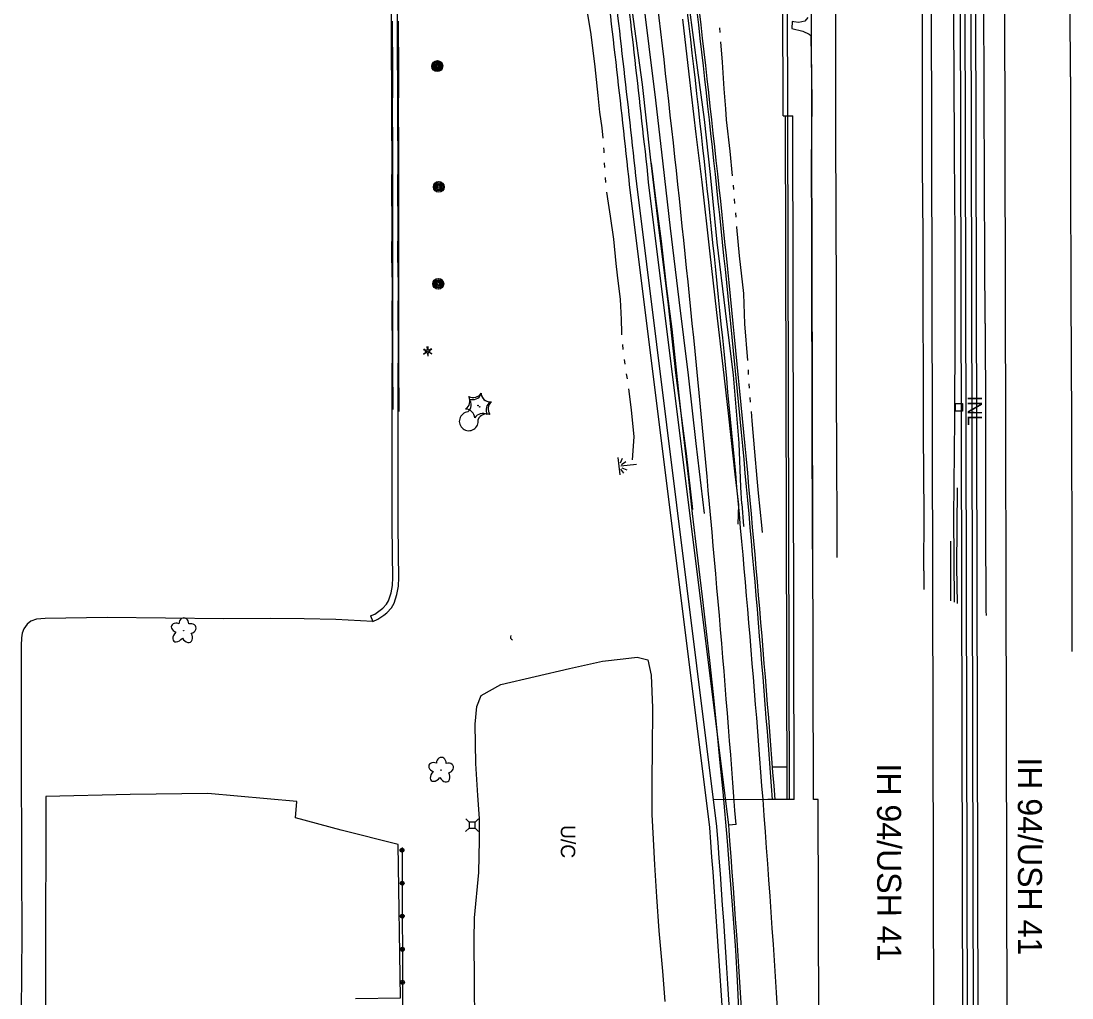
# Model space of a CAD drawing. Extents: x 588843 to 2552415, y 180129 to 269402.
# Drawn here: x 593621.5 to 594059.5, y 184401.2 to 184808.3 of the extents above; entities that cross this region are included whole.
import ezdxf

# ---------------------------------------------------------------- set-up
doc = ezdxf.new("R2010")
doc.units = 0
for name, color, linetype in [('Default', 7, 'Continuous'), ('E_AREA', 7, 'Continuous'), ('E_AREA_Text', 7, 'Continuous'), ('E_BMGRD_P', 7, 'Continuous'), ('E_DRN', 7, 'Continuous'), ('E_DRN_Text', 7, 'Continuous'), ('E_DWY', 7, 'Continuous'), ('E_LAND_Vegetation', 7, 'Continuous'), ('E_LTG', 7, 'Continuous'), ('E_MISCPROP', 7, 'Continuous'), ('E_RDWY', 7, 'Continuous'), ('E_RDWY_C_and_G', 7, 'Continuous'), ('E_RDWY_Gravel', 7, 'Continuous'), ('E_RDWY_Text', 7, 'Continuous'), ('E_STRUCT', 7, 'Continuous'), ('E_UTL_AG_Bold', 7, 'Continuous'), ('E_WTR_P', 7, 'Continuous'), ('E_WTR_Wetland', 7, 'Continuous'), ('P_RDWY_BarrierConc', 7, 'Continuous'), ('P_RDWY_C_and_G', 7, 'Continuous'), ('P_RDWY_C_and_GBack', 7, 'Continuous'), ('P_RDWY_C_and_GFace', 7, 'Continuous'), ('P_RDWY_LaneEdge', 7, 'Continuous'), ('P_RDWY_PavtEdge', 7, 'Continuous'), ('P_RDWY_ShldAgg', 7, 'Continuous'), ('P_RDWY_ShldPaved', 7, 'Continuous')]:
    doc.layers.add(name, color=color, linetype=linetype)

# ---------------------------------------------------------------- blocks, each defined once
blk = doc.blocks.new('DTRE')
at = {"layer": 'Default'}
blk.add_circle((-0.18, 0), 0.183, dxfattribs=at)
for centre, major_axis, ratio in [((-1.87, 5.32), (1.36, -4.98), 0.782863), ((-5.87, 0.15), (4.93, -0.12), 0.832022), ((4.06, 2.74), (-5.27, -2.93), 0.691916), ((-2.49, -5.24), (1.8, 4.86), 0.716896), ((3.54, -3.71), (-5.01, 4.58), 0.560249)]:
    blk.add_ellipse(centre, major_axis=major_axis, ratio=ratio, start_param=1.570796, end_param=4.712389, dxfattribs=at)
blk = doc.blocks.new('LPOL')
at = {"layer": 'Default'}
for p, q in [((-4, 0), (-1.5, 0)), ((-0.75, 1.3), (-2, 3.46)), ((0.75, 1.3), (2, 3.46)), ((1.5, 0), (4, 0)), ((-2, -3.46), (-0.75, -1.3)), ((2, -3.46), (0.75, -1.3))]:
    blk.add_line(p, q, dxfattribs=at)
for radius in [1.5, 1.5, 1.5, 0.125]:
    blk.add_circle((0, 0), radius, dxfattribs=at)
blk = doc.blocks.new('POLE')
at = {"layer": 'Default'}
for radius in [4.46, 3.35, 2.23, 1.12]:
    blk.add_circle((0, 0), radius, dxfattribs=at)
blk = doc.blocks.new('CTRE')
at = {"layer": 'Default'}
blk.add_circle((0, 0), 0.223, dxfattribs=at)
for centre, start, end in [((-11.97, 8.96), 280.2067, 5.97162), ((1.81, 14.92), 220.21132, 305.97623), ((-13.83, -5.9), 340.21132, 65.97623), ((13.83, 5.89), 160.21133, 245.97624), ((-1.81, -14.93), 40.21133, 125.97624), ((12.03, -9.04), 185.92721, 100.25111)]:
    blk.add_arc(centre, 7.87, start, end, dxfattribs=at)
blk = doc.blocks.new('PED')
at = {"layer": 'Default'}
for p, q in [((-2.5, 2.5), (-5.33, 5.33)), ((2.5, 2.5), (5.33, 5.33)), ((-2.5, -2.5), (-5.33, -5.33)), ((2.5, -2.5), (5.33, -5.33))]:
    blk.add_line(p, q, dxfattribs=at)
blk.add_lwpolyline([(-2.5, -2.5), (2.5, -2.5), (2.5, 2.5), (-2.5, 2.5)], close=True, dxfattribs=at)
blk = doc.blocks.new('CULV2')
at = {"layer": 'E_DRN'}
blk.add_arc((19.7, 14.8), 24.6, 216.8699, 323.1301, dxfattribs=at)
blk = doc.blocks.new('UCA_1')
at = {"layer": 'E_AREA_Text'}
blk.add_text('U/C', height=12, dxfattribs=at).set_placement((-15.33, -6))
blk = doc.blocks.new('INLT_47_1')
at = {"layer": 'E_DRN_Text'}
blk.add_text('INL', height=39.37, dxfattribs=at).set_placement((-36.2, -19.7))
blk = doc.blocks.new('MAR_3')
at = {"layer": 'E_WTR_Wetland'}
for p, q in [((-0.1, 48.7), (-0.1, 5.3)), ((-24, 0), (23.7, 0)), ((-20, 11.5), (-8.1, 4.8)), ((-4.5, 7.8), (-11.6, 20.2)), ((4.6, 7.8), (11.7, 20.2)), ((20, 11.5), (8.1, 4.8))]:
    blk.add_line(p, q, dxfattribs=at)
blk = doc.blocks.new('LPOL_4')
at = {"layer": 'E_LTG'}
for p, q in [((-13.1, 0), (-4.9, 0)), ((-2.5, 4.3), (-6.6, 11.4)), ((2.5, 4.3), (6.6, 11.4)), ((4.9, 0), (13.1, 0)), ((-6.6, -11.4), (-2.5, -4.3)), ((6.6, -11.4), (2.5, -4.3))]:
    blk.add_line(p, q, dxfattribs=at)
for radius in [4.92, 4.92, 4.92, 0.41]:
    blk.add_circle((0, 0), radius, dxfattribs=at)
blk = doc.blocks.new('POLE_3')
at = {"layer": 'E_MISCPROP'}
for radius in [14.6, 11, 7.32, 3.66]:
    blk.add_circle((0, 0), radius, dxfattribs=at)
blk = doc.blocks.new('CTRE_4')
at = {"layer": 'E_LAND_Vegetation'}
blk.add_circle((0, 0), 0.733, dxfattribs=at)
for centre, start, end in [((-39.3, 29.4), 280.2067, 5.9716), ((5.9, 49), 220.2113, 305.9762), ((-45.4, -19.3), 340.2113, 65.9762), ((45.4, 19.3), 160.2113, 245.9762), ((-5.9, -49), 40.2113, 125.9762), ((39.5, -29.6), 100.2511, 185.9272)]:
    blk.add_arc(centre, 25.8, start, end, dxfattribs=at)

msp = doc.modelspace()

# ---------------------------------------------------------------- linework, layer by layer
at = {"layer": 'E_AREA'}
msp.add_lwpolyline([(593810.77, 184373.26), (593810.42, 184425.33), (593810.56, 184434.56), (593812.35, 184453.43), (593812.6, 184466.99), (593812.54, 184475.91), (593811.88, 184485.55), (593811.1, 184498.88), (593810.79, 184515.27), (593811.49, 184522.6), (593813.24, 184527.19), (593821.47, 184531.84), (593850.1, 184538.48), (593863.86, 184541.49), (593872.45, 184542.57), (593878.31, 184543.15), (593882.76, 184542.11), (593884.2, 184535.68), (593884.7, 184522.05), (593884.5, 184504.28), (593884.37, 184492.57), (593884.45, 184477.64), (593884.95, 184467.29), (593885.57, 184456.69), (593886.35, 184443.37), (593887.4, 184429.14), (593888.88, 184412.4), (593889.82, 184399.75)], dxfattribs=at)
at = {"layer": 'E_BMGRD_P'}
msp.add_lwpolyline([(593780.31, 184463.92), (593780.54, 184391.32), (593780.57, 184330.59), (593780.68, 184274.1), (593780.2, 184209.84), (593780.05, 184155.08), (593779.93, 184133.47)], dxfattribs=at)
for centre, major_axis in [((593780.31, 184462.77), (0.015, 0.802)), ((593780.31, 184462.77), (0.007, 0.404)), ((593780.36, 184449), (0.015, 0.802)), ((593780.36, 184449), (0.007, 0.404)), ((593780.4, 184435.24), (0.015, 0.802)), ((593780.4, 184435.24), (0.007, 0.404)), ((593780.45, 184421.47), (0.015, 0.802)), ((593780.45, 184421.47), (0.007, 0.404)), ((593780.49, 184407.7), (0.015, 0.802)), ((593780.49, 184407.7), (0.007, 0.404))]:
    msp.add_ellipse(centre, major_axis=major_axis, ratio=0.996114, dxfattribs=at)
at = {"layer": 'E_DRN'}
msp.add_lwpolyline([(594013.86, 184648.93), (594013.94, 184645.78), (594011.04, 184645.71), (594010.96, 184648.86)], close=True, dxfattribs=at)
at = {"layer": 'E_DWY'}
for points in [[(593776.15, 184749.37), (593776.03, 184767.18), (593776.04, 184780.71), (593775.97, 184794.73), (593775.97, 184811.77)], [(593778.65, 184749.39), (593778.53, 184767.19), (593778.54, 184780.71), (593778.47, 184794.73), (593778.47, 184811.77)], [(593776.19, 184808.3), (593776.28, 184786.65), (593776.22, 184765.56), (593776.28, 184762.73), (593776.35, 184744.69), (593776.37, 184730.05), (593776.29, 184709.98), (593776.31, 184688.06), (593776.35, 184665.26), (593776.43, 184646.46)], [(593778.69, 184808.31), (593778.78, 184786.65), (593778.72, 184765.59), (593778.78, 184762.76), (593778.85, 184744.69), (593778.87, 184730.05), (593778.79, 184709.98), (593778.81, 184688.06), (593778.85, 184665.27), (593778.94, 184645.66), (593778.94, 184645.61)], [(593767.19, 184560.4), (593768.98, 184561.17), (593771.24, 184562.73), (593772.3, 184563.56), (593773.86, 184565.27), (593774.71, 184566.73), (593775.76, 184569.96), (593776.29, 184573.05), (593776.45, 184576.4), (593776.4, 184585.97), (593776.21, 184598.89), (593776.23, 184612.99), (593776.2, 184630.31), (593776.27, 184643.59), (593776.22, 184658.3), (593776.29, 184673.42), (593776.21, 184685.03), (593776.36, 184698.52), (593776.13, 184710.52), (593776.19, 184722.71), (593776.12, 184739.48), (593776.15, 184749.37)], [(593768.18, 184558.11), (593770.2, 184558.97), (593772.72, 184560.71), (593774.01, 184561.72), (593775.88, 184563.78), (593777, 184565.7), (593778.19, 184569.36), (593778.78, 184572.77), (593778.95, 184576.35), (593778.9, 184586), (593778.71, 184598.91), (593778.73, 184612.99), (593778.7, 184630.31), (593778.77, 184643.58), (593778.72, 184658.29), (593778.79, 184673.42), (593778.71, 184685.03), (593778.86, 184698.53), (593778.63, 184710.53), (593778.69, 184722.71), (593778.62, 184739.48), (593778.65, 184749.39)], [(593767.19, 184560.4), (593768.18, 184558.11), (593752.76, 184558.88), (593739.58, 184559.14), (593725.35, 184559.27), (593705.98, 184559.23), (593657.46, 184559.7), (593631.52, 184559.25), (593627.9, 184559), (593625.55, 184558.15), (593624.05, 184556.99), (593622.66, 184555.07), (593621.99, 184553.25), (593621.65, 184551.31), (593621.53, 184548.04), (593621.56, 184505.7), (593621.71, 184455.38), (593621.85, 184427.62), (593621.52, 184395.34)], [(593760.97, 184400.9), (593779.66, 184401.18), (593778.67, 184465.17), (593755, 184471.17), (593735.86, 184476.24), (593736.4, 184483.08), (593699.43, 184486.32), (593666.97, 184486.03), (593631.87, 184485.11), (593631.69, 184413.71), (593631.67, 184373.35)]]:
    msp.add_lwpolyline(points, dxfattribs=at)
at = {"layer": 'E_RDWY'}
for points in [[(594023.34, 184682.26), (594023.25, 184709.56), (594023.04, 184739.91), (594023, 184778.2), (594022.82, 184818.16), (594022.67, 184861.06), (594022.65, 184896.86), (594022.58, 184934.07), (594022.62, 184972.8), (594022.48, 185013.2), (594022.39, 185057.62), (594022.2, 185103.22), (594022.12, 185147.96), (594021.99, 185189.79), (594021.86, 185234.19), (594021.61, 185282.87), (594021.71, 185325.21), (594022.01, 185370.2), (594022.14, 185393.45)], [(594058.92, 184785.01), (594058.82, 184814.32), (594058.74, 184856.48), (594058.72, 184888.42), (594058.64, 184920.39), (594058.61, 184955.57), (594058.47, 184990.54), (594058.38, 185026.41), (594058.18, 185063.12), (594058.32, 185096.32), (594058.13, 185129.63), (594058.04, 185158.77), (594058.03, 185187.99), (594057.99, 185226.54), (594057.97, 185253.66), (594057.64, 185280.67), (594057.82, 185338.96), (594057.67, 185356.32), (594057.68, 185378.51)], [(593906.33, 184603.12), (593902.92, 184632.27), (593899.65, 184660.76), (593895.88, 184692.09), (593892.24, 184722.03), (593889.11, 184748.84), (593886.03, 184775.27), (593883.34, 184797.63), (593880.29, 184822.58), (593876.81, 184852.9), (593873.76, 184879.56), (593870.15, 184910.6), (593867.01, 184938.51), (593863.39, 184971.22), (593860.52, 184996.66), (593857.95, 185023.1), (593855.61, 185048.62), (593852.95, 185083.15), (593851.06, 185119.17), (593850.2, 185152.54), (593849.72, 185184.93), (593849.66, 185210.92)], [(593961.66, 184584.71), (593961.61, 184597.79), (593961.51, 184627.2), (593961.41, 184654.59), (593961.38, 184693.93), (593961.28, 184727.64), (593961.06, 184762.04), (593961.05, 184801.45), (593960.9, 184844.07), (593960.93, 184878.06), (593960.81, 184909.45), (593960.59, 184947.71), (593960.4, 184982.2), (593960.44, 185016.64), (593960.35, 185048.64), (593960.38, 185082.04), (593960.11, 185118.13), (593960.11, 185156.58), (593960.05, 185202.8)], [(593997.74, 184579.23), (593997.88, 184602.77), (593997.66, 184636.35), (593997.62, 184658.68), (593997.56, 184689.47), (593997.45, 184718.98), (593997.28, 184748.08), (593997.28, 184776.99), (593997.26, 184803.01), (593997.03, 184828.04), (593997.04, 184853.56), (593997.01, 184872.9), (593996.93, 184898.91), (593996.95, 184927.32), (593996.91, 184954.55), (593996.75, 184983.68), (593996.74, 185009.24), (593996.75, 185039.17), (593996.69, 185065.27), (593996.43, 185092.39), (593996.46, 185124.29), (593996.36, 185155.17), (593996.3, 185186.28)], [(593897.19, 184809.08), (593899.84, 184786.18), (593902.76, 184761.17), (593905.25, 184741.14), (593908.51, 184712.48), (593911.44, 184686.85), (593913.95, 184664.33), (593916.36, 184643.6), (593919.08, 184619.5), (593920.48, 184606.75)], [(594058.92, 184785.01), (594058.88, 184744.07), (594059.07, 184694.66), (594059.28, 184640.64), (594059.48, 184584.47), (594059.53, 184545.63)], [(594023.34, 184682.26), (594023.42, 184643.54), (594023.53, 184599.58), (594023.69, 184562.57), (594023.7, 184560.56)], [(593997.74, 184579.23), (593997.77, 184571.36)]]:
    msp.add_lwpolyline(points, dxfattribs=at)
at = {"layer": 'E_RDWY_C_and_G'}
for points in [[(593920.48, 184606.75), (593920.23, 184598.56)], [(593922, 184607.06), (593922.69, 184597.87), (593922.71, 184597.72)]]:
    msp.add_lwpolyline(points, dxfattribs=at)
at = {"layer": 'E_RDWY_Gravel'}
for points in [[(593901.51, 184604.7), (593898.89, 184628.12), (593894.48, 184661.7), (593891.4, 184689.97), (593887.19, 184723.53), (593883.88, 184751.61), (593880.49, 184781.82), (593876.8, 184809.14), (593872.09, 184846.12), (593868.13, 184880.53), (593863.95, 184918.6), (593860.69, 184948.98), (593857.26, 184982.17), (593854.92, 185005.52), (593852.06, 185032.14), (593849.54, 185060.16), (593847.3, 185092.17), (593846.04, 185116.76), (593845.29, 185144.85), (593844.4, 185173.99), (593844.28, 185200.35)], [(593921.9, 184607.05), (593921.46, 184614), (593920.76, 184632.41), (593918.41, 184660.66), (593915.16, 184687.58), (593911.66, 184716.17), (593908.93, 184744.38), (593906.44, 184767.23), (593903.57, 184787.84), (593900.04, 184815.06)], [(593949.5, 184809.8), (593948.2, 184808.25), (593945.74, 184807.72), (593943.63, 184807.97), (593942.94, 184808.04), (593942.74, 184805.25), (593947.41, 184804.12), (593950.05, 184802.84), (593950.73, 184802.31), (593951.07, 184775.26), (593950.85, 184747.91), (593950.97, 184721.39), (593951.02, 184689.79), (593951.09, 184659.68), (593951.11, 184632.56), (593951.21, 184602.44), (593951.27, 184588.18)], [(593884.18, 184749.05), (593885.95, 184734.32), (593888.25, 184716.51), (593890.39, 184697.91), (593892.71, 184679.87), (593894.39, 184664.15), (593895.66, 184652.37), (593897.4, 184637.41), (593899.65, 184617.33), (593901.24, 184603.07), (593902.64, 184591.34), (593905.43, 184568.31), (593906.88, 184555.12), (593908.47, 184541.75), (593909.96, 184527.7), (593911.46, 184512.53), (593912.57, 184500.57), (593914.01, 184487.1), (593915.76, 184466.58), (593916.76, 184453.61), (593917.86, 184439.82), (593919.24, 184421.13), (593919.93, 184408.32), (593920.5, 184396.58)], [(594011.74, 184613.72), (594011.45, 184580.83), (594011.72, 184565.55)], [(594008.93, 184591.49), (594008.96, 184566.69)]]:
    msp.add_lwpolyline(points, dxfattribs=at)
at = {"layer": 'E_STRUCT'}
for points in [[(594007.57, 185399.67), (594008.45, 185379.96), (594008.58, 185346.39), (594008.62, 185302.69), (594008.59, 185270.63), (594008.85, 185235.62), (594008.95, 185198.53), (594009.16, 185161.43), (594009.23, 185125.36), (594009.42, 185092.69), (594009.24, 185064.46), (594009.4, 185031), (594009.61, 184996.11), (594009.68, 184962.18), (594009.8, 184932.13), (594009.91, 184898.48), (594010.17, 184858.49), (594010.07, 184823.02), (594010.32, 184787.4), (594010.45, 184753.11), (594010.69, 184718.6), (594010.65, 184679.45), (594010.55, 184642.38), (594010.12, 184601.49)], [(594010.12, 184601.49), (594010.41, 184566.09)]]:
    msp.add_lwpolyline(points, dxfattribs=at)
at = {"layer": 'E_WTR_P'}
for points in [[(593856.64, 184818.82), (593857.32, 184812.83), (593859.06, 184802.75), (593860.6, 184789.22)], [(593912.65, 184805.42), (593912.75, 184803.49)], [(593913.05, 184799.64), (593913.75, 184791.12), (593914.44, 184780.11), (593915.07, 184771.69)], [(593860.6, 184789.22), (593860.9, 184786.6), (593861.94, 184777.29), (593862.64, 184770.28), (593863.53, 184763.77), (593863.94, 184759.53)], [(593915.07, 184771.69), (593915.41, 184767.09), (593916.91, 184754.06), (593917.89, 184743.82)], [(593864.33, 184755.43), (593864.44, 184754.34), (593864.47, 184753.38)], [(593864.61, 184749.26), (593864.68, 184747.2)], [(593864.96, 184743.09), (593865.16, 184741.04)], [(593865.59, 184736.94), (593866.2, 184732.38), (593867.01, 184726.97), (593868.42, 184717.34), (593869.47, 184707.32)], [(593918.26, 184739.97), (593918.44, 184738.05)], [(593918.78, 184734.2), (593918.94, 184732.27)], [(593919.27, 184728.42), (593919.43, 184726.5)], [(593919.76, 184722.65), (593919.77, 184722.46), (593920.89, 184710.46), (593922.58, 184694.77)], [(593869.47, 184707.32), (593869.99, 184702.34), (593871.27, 184692.29), (593871.69, 184683.98), (593871.76, 184678.48), (593871.84, 184677.57)], [(593922.58, 184694.77), (593922.59, 184694.68), (593923.05, 184682.11), (593924.26, 184666.81)], [(593872.2, 184673.46), (593872.38, 184671.41)], [(593872.84, 184667.32), (593873.15, 184665.28)], [(593924.53, 184662.96), (593924.64, 184661.03)], [(593873.77, 184661.21), (593874.08, 184659.17)], [(593924.87, 184657.17), (593924.99, 184655.24)], [(593874.68, 184655.09), (593875.79, 184646.33), (593876.96, 184635.03), (593876.17, 184625.39)], [(593925.29, 184651.39), (593925.46, 184649.46)], [(593925.81, 184645.62), (593926.17, 184641.63), (593927.16, 184628.84), (593928.16, 184617.7)], [(593928.16, 184617.7), (593928.71, 184611.54), (593930.1, 184598.18), (593930.41, 184595.14)]]:
    msp.add_lwpolyline(points, dxfattribs=at)
at = {"layer": 'P_RDWY_BarrierConc'}
for p, q in [((594015.52, 183703.15), (594011.71, 185400.89)), ((594017.52, 183703.15), (594013.71, 185400.03)), ((594020.02, 183703.16), (594016.21, 185398.95)), ((594022.02, 183703.16), (594018.21, 185398.08)), ((593941.13, 184768.81), (593939.74, 185387.02)), ((593939.13, 184768.81), (593938.5, 185047.43)), ((593939.13, 184768.81), (593943.13, 184768.82))]:
    msp.add_line(p, q, dxfattribs=at)
at = {"layer": 'P_RDWY_C_and_G'}
for q in [(593943.13, 184768.82), (593932.77, 184483.89)]:
    msp.add_line((593943.77, 184483.92), q, dxfattribs=at)
msp.add_arc((585838.74, 183873.64), 8115, 4.312666, 6.879896, dxfattribs=at)
at = {"layer": 'P_RDWY_C_and_GBack'}
msp.add_line((593940.77, 184483.91), (593940.13, 184768.81), dxfattribs=at)
msp.add_arc((585838.74, 183873.64), 8120, 4.310168, 6.879896, dxfattribs=at)
at = {"layer": 'P_RDWY_C_and_GFace'}
msp.add_line((593941.77, 184483.91), (593941.13, 184768.81), dxfattribs=at)
msp.add_arc((585838.74, 183873.64), 8119, 4.310168, 6.879896, dxfattribs=at)
at = {"layer": 'P_RDWY_LaneEdge'}
msp.add_line((593919.51, 184473.48), (593916.51, 184473.26), dxfattribs=at)
msp.add_arc((585838.74, 183873.64), 8103, 4.245358, 6.879896, dxfattribs=at)
at = {"layer": 'P_RDWY_PavtEdge'}
for p, q in [((594003.52, 183703.12), (593999.78, 185371.14)), ((594034.02, 183703.19), (594030.35, 185336.23)), ((593916.51, 184473.26), (593883.1, 184741.14)), ((593934.74, 184497.49), (593940.74, 184497.51)), ((593932.77, 184483.89), (593910.17, 184483.72)), ((593953.77, 184483.94), (593951.77, 184483.94)), ((593955.52, 183703.01), (593953.77, 184483.94))]:
    msp.add_line(p, q, dxfattribs=at)
for radius, start, end in [(8091, 6.154981, 6.879896), (8115, 1.274493, 4.312666), (8100, 1.274493, 4.245358)]:
    msp.add_arc((585838.74, 183873.64), radius, start, end, dxfattribs=at)
at = {"layer": 'P_RDWY_ShldAgg'}
msp.add_line((593908.58, 184472.27), (593875.16, 184740.15), dxfattribs=at)
for radius, start, end in [(8083, 6.154981, 6.879896), (8092, 1.434819, 4.242526)]:
    msp.add_arc((585838.74, 183873.64), radius, start, end, dxfattribs=at)
at = {"layer": 'P_RDWY_ShldPaved'}
for p, q in [((593951.77, 184483.94), (593949.78, 185371.03)), ((593911.55, 184472.64), (593878.14, 184740.52)), ((593941.3, 184693.91), (593941.3, 184693.91)), ((593941.3, 184691.91), (593941.3, 184691.91))]:
    msp.add_line(p, q, dxfattribs=at)
for radius, start, end in [(8086, 6.154981, 6.879896), (8095, 1.274493, 4.242526)]:
    msp.add_arc((585838.74, 183873.64), radius, start, end, dxfattribs=at)

# ---------------------------------------------------------------- block references
at = {"layer": 'E_AREA_Text', "xscale": 0.49999999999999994, "yscale": 0.5, "rotation": -90.03098035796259}
msp.add_blockref('UCA_1', (593849.5, 184465.58), dxfattribs=at)
at = {"layer": 'E_DRN', "xscale": 0.047935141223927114, "yscale": 0.04793514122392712, "rotation": -67.4475049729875}
msp.add_blockref('CULV2', (593825.66, 184552.2), dxfattribs=at)
at = {"layer": 'E_DRN_Text', "xscale": 0.1524003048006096, "yscale": 0.1524003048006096, "rotation": -90.21819803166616}
msp.add_blockref('INLT_47_1', (594019.06, 184646.62), dxfattribs=at)
at = {"layer": 'E_LAND_Vegetation'}
for name, p, xscale, yscale, rotation in [('CTRE', (593812.65, 184647.53), 0.49999999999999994, 0.5, -90.03098035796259), ('CTRE_4', (593811.97, 184648.08), 0.1524003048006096, 0.1524003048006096, -97.36026881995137), ('DTRE', (593689.29, 184554.17), 0.49999999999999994, 0.5, -90.03098035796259), ('DTRE', (593796.59, 184496.04), 0.49999999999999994, 0.5, -90.03098035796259)]:
    msp.add_blockref(name, p, dxfattribs=dict(at, xscale=xscale, yscale=yscale, rotation=rotation))
at = {"layer": 'E_LTG'}
for name, p, xscale, yscale, rotation in [('LPOL_4', (593790.9, 184670.64), 0.1524003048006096, 0.15240030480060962, -84.36014555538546), ('LPOL', (593791.06, 184670.65), 0.49999999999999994, 0.5, -90.03098035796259)]:
    msp.add_blockref(name, p, dxfattribs=dict(at, xscale=xscale, yscale=yscale, rotation=rotation))
at = {"layer": 'E_MISCPROP'}
for name, p, xscale, yscale, rotation in [('POLE_3', (593795.05, 184789.57), 0.1524003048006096, 0.15240030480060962, -84.36014555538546), ('POLE', (593794.98, 184789.44), 0.5000000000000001, 0.5, -90.72490345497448), ('POLE_3', (593795.65, 184739.16), 0.1524003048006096, 0.15240030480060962, -84.36014555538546), ('POLE', (593795.59, 184739.2), 0.49999999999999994, 0.5, -90.03098035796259), ('POLE_3', (593795.45, 184698.82), 0.1524003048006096, 0.15240030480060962, -84.36014555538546), ('POLE', (593795.34, 184698.78), 0.49999999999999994, 0.5, -90.03098035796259)]:
    msp.add_blockref(name, p, dxfattribs=dict(at, xscale=xscale, yscale=yscale, rotation=rotation))
at = {"layer": 'E_UTL_AG_Bold', "xscale": 0.49999999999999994, "yscale": 0.5, "rotation": -90.03098035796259}
msp.add_blockref('PED', (593809.5, 184473.19), dxfattribs=at)
at = {"layer": 'E_WTR_Wetland', "xscale": 0.1524003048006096, "yscale": 0.1524003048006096, "rotation": -83.62694580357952}
msp.add_blockref('MAR_3', (593870.69, 184622.71), dxfattribs=at)

# ---------------------------------------------------------------- texts
at = {"layer": 'E_RDWY_Text'}
for p in [(594036.96, 184501.46), (593978.27, 184498.91)]:
    msp.add_text('IH 94/USH 41', height=10, rotation=270.0909, dxfattribs=at).set_placement(p)

doc.saveas('drawing.dxf')
